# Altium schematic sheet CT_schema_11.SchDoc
size 388 x 278 mm
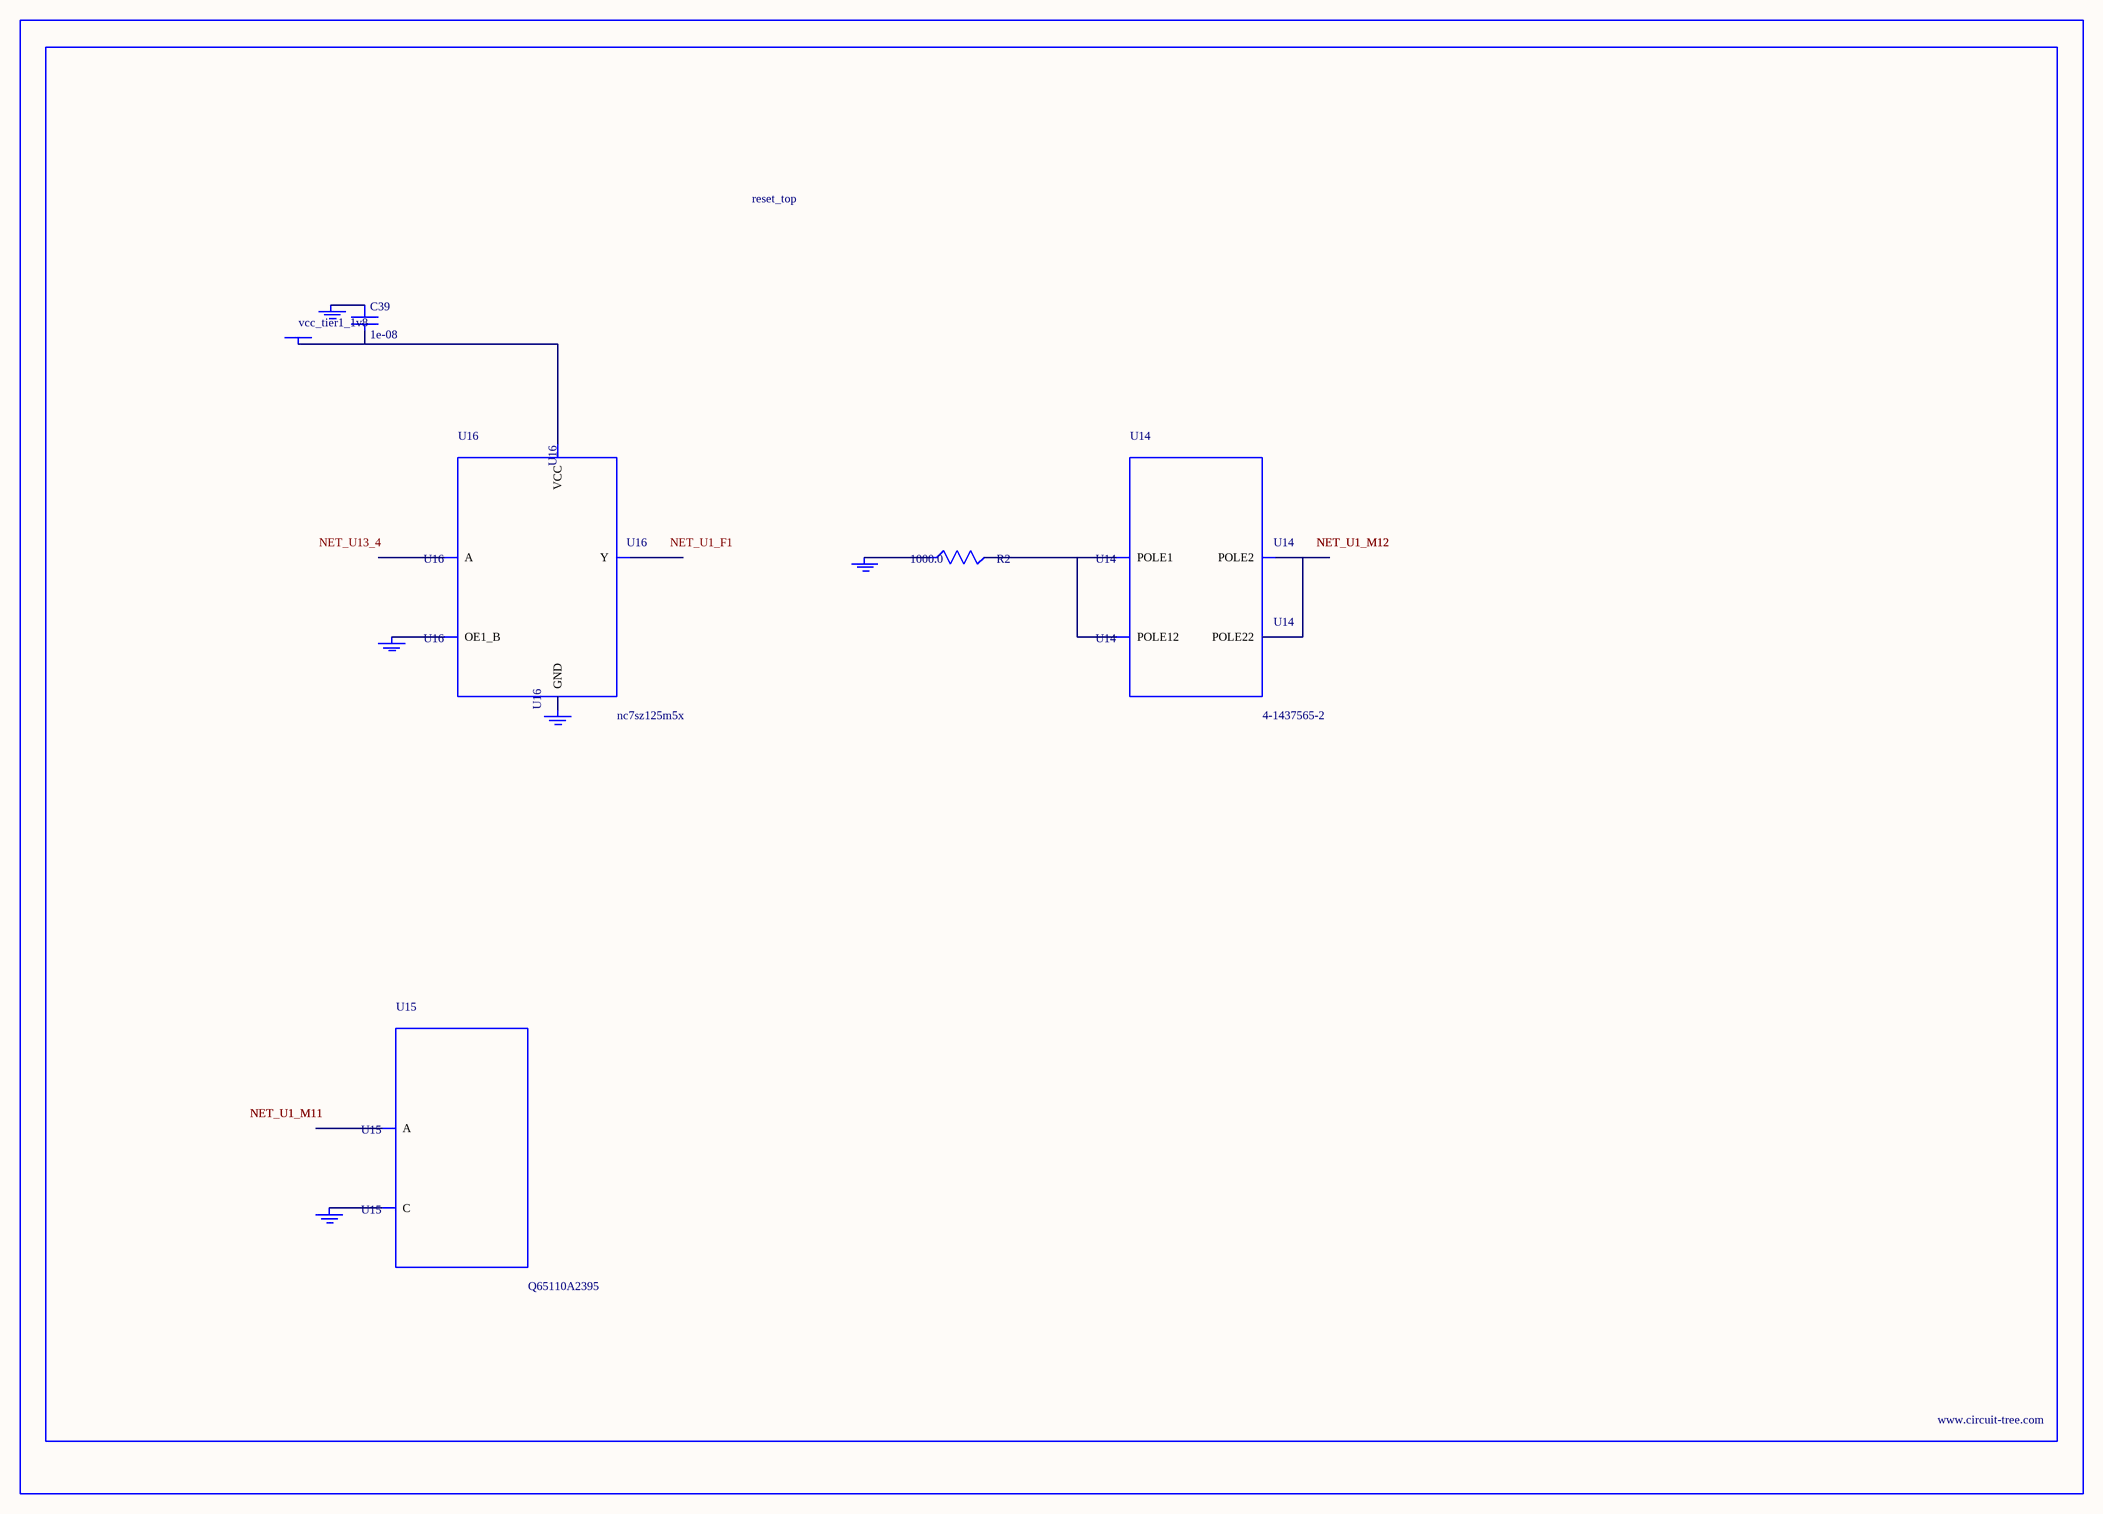
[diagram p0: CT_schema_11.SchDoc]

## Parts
BORDER10  (no value)
C39  1e-08  [C0402]
GND_INSTANCE_10_0  (no value)
GND_INSTANCE_10_1  (no value)
GND_INSTANCE_10_2  (no value)
GND_INSTANCE_10_3  (no value)
GND_INSTANCE_10_4  (no value)
POWER_INSTANCE_10_0  vcc_tier1_1v8
R2  1000.0  [R0603]
U14  4-1437565-2  [SW_4-1437565-2]
U15  Q65110A2395  [LGM67K-G1J2-24-Z]
U16  nc7sz125m5x  [NC7SZ125M5X]

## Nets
NetC39_1: C39.1 GND_INSTANCE_10_2.0(GND)
NetC39_2: C39.2 POWER_INSTANCE_10_0.0(PWR) U16.5(VCC)
NetGND_INSTANCE_10_0_0: GND_INSTANCE_10_0.0(GND) R2.1
NetGND_INSTANCE_10_1_0: GND_INSTANCE_10_1.0(GND) U15.C
NetGND_INSTANCE_10_3_0: GND_INSTANCE_10_3.0(GND) U16.1(OE1_B)
NetGND_INSTANCE_10_4_0: GND_INSTANCE_10_4.0(GND) U16.3(GND)
NetR2_2: R2.2 U14.1(POLE1) U14.2(POLE12)
NetU14_3: U14.3(POLE2) U14.4(POLE22)

Not connected (* = marked no-connect by the designer): U15 A; U16 2(A) 4(Y)

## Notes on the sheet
- Labels drawn without touching a wire or pin: NET_U1_F1, NET_U13_4

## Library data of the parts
BORDER10 = BORDER_PAGE10
C39 = C0402C103K3RAC
GND_INSTANCE_10_0-GND_INSTANCE_10_4 = GND
POWER_INSTANCE_10_0 = PWR
R2 = RC0603JR-071KL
